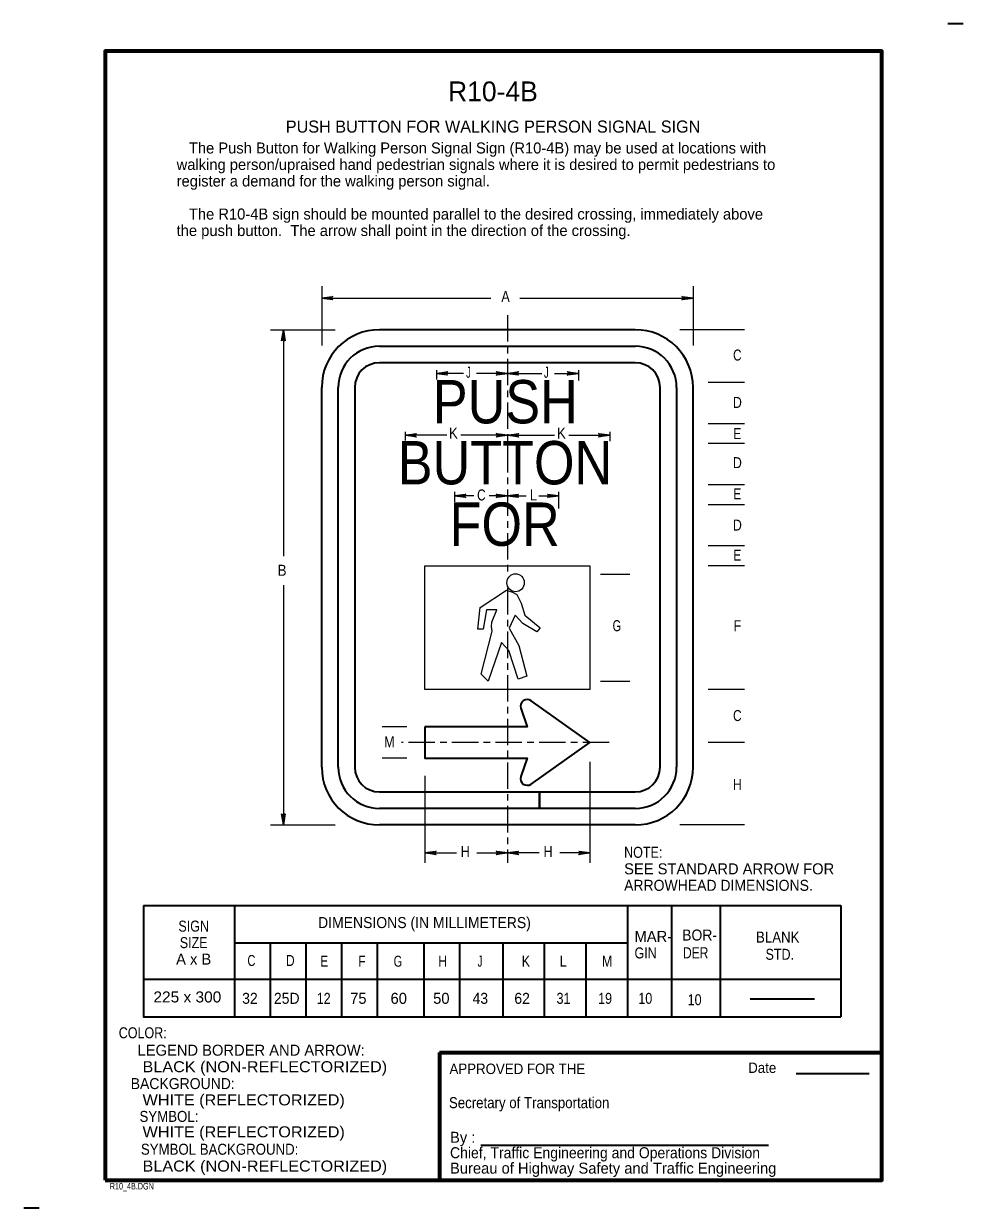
# Model space of a CAD drawing. Extents: x -13 to 209, y -30 to 60.
# Drawn here: x -12.67 to 8.68, y -16.28 to 10.63 of the extents above; entities that cross this region are included whole.
import ezdxf
from ezdxf.enums import TextEntityAlignment as Align

# ---------------------------------------------------------------- set-up
doc = ezdxf.new("R2010")
doc.units = 0
doc.header["$LTSCALE"] = 0.1
doc.linetypes.add('LONG_DASH_SHORT_DASH', pattern=[9.9, 6, -1.2, 1.5, -1.2])
doc.layers.add('1', color=7, linetype='Continuous', lineweight=35)
doc.layers.add('3', color=7, linetype='Continuous', lineweight=35)

msp = doc.modelspace()

# ---------------------------------------------------------------- linework, layer by layer
at = {"layer": '1'}
for p, q in [((8.6843, 10.633), (8.3343, 10.633)), ((4.8842, -13.217), (6.5468, -13.217)), ((-2.2782, -14.842), (4.2592, -14.842)), ((-12.3157, -16.2795), (-12.6658, -16.2795))]:
    msp.add_line(p, q, dxfattribs=at)
at = {"layer": '1', "lineweight": 70}
for q in [(6.8342, -12.742), (-3.2157, -15.642)]:
    msp.add_line((-3.2157, -12.742), q, dxfattribs=at)
msp.add_lwpolyline([(-10.8157, -15.642), (6.8342, -15.642), (6.8342, 10.008), (-10.8157, 10.008)], close=True, dxfattribs=at)
at = {"layer": '3', "lineweight": 25}
for p, q in [((-5.8936, 4.6688), (-5.8936, 3.3195)), ((2.5439, 4.6688), (2.5439, 3.3195)), ((-5.8936, 4.3976), (-2.0528, 4.3976)), ((-1.393, 4.3976), (2.5439, 4.3976)), ((-7.0587, 3.6803), (-5.5905, 3.6803)), ((-6.7644, 3.6803), (-6.7644, -1.4665)), ((3.709, 3.6803), (2.2408, 3.6803)), ((-3.2874, 2.7626), (-3.2874, 2.5488)), ((-0.0624, 2.7626), (-0.0624, 2.5305)), ((-2.6729, 2.6881), (-3.2874, 2.6881)), ((-1.6749, 2.6881), (-2.3796, 2.6881)), ((-1.6749, 2.6881), (-0.8889, 2.6881)), ((-0.6079, 2.6881), (-0.0624, 2.6881)), ((3.709, 2.4802), (2.8895, 2.4802)), ((-3.9999, 1.3631), (-3.9999, 1.1615)), ((0.6501, 1.3631), (0.6501, 1.1493)), ((3.709, 1.5428), (2.8895, 1.5428)), ((-3.0516, 1.2825), (-3.9999, 1.2825)), ((-1.6749, 1.2825), (-2.734, 1.2825)), ((-1.6749, 1.2825), (-0.6018, 1.2825)), ((-0.278, 1.2825), (0.6501, 1.2825)), ((3.709, 1.0928), (2.8895, 1.0928)), ((3.709, 0.1552), (2.8895, 0.1552)), ((-2.8749, -0.0059), (-2.8749, -0.2259)), ((-2.4407, -0.0926), (-2.8749, -0.0926)), ((-1.6749, -0.0926), (-2.0864, -0.0926)), ((-1.6749, -0.0926), (-1.2494, -0.0926)), ((-0.9623, -0.0926), (-0.5124, -0.0926)), ((-0.5124, -0.0059), (-0.5124, -0.3786)), ((3.709, -0.2948), (2.8895, -0.2948)), ((3.709, -1.2323), (2.8895, -1.2323)), ((0.4395, -1.8725), (1.1096, -1.8725)), ((3.709, -1.6823), (2.8895, -1.6823)), ((-6.7644, -2.1265), (-6.7644, -7.5697)), ((0.4395, -4.3045), (1.1096, -4.3045)), ((3.709, -4.4947), (2.8895, -4.4947)), ((-3.959, -5.3385), (-4.521, -5.3385)), ((3.709, -5.6947), (2.8895, -5.6947)), ((-3.959, -6.051), (-4.521, -6.051)), ((0.2001, -6.1357), (0.2001, -8.4337)), ((-3.5499, -6.4536), (-3.5499, -8.4337)), ((-7.0587, -7.5697), (-5.5905, -7.5697)), ((3.709, -7.5697), (2.2408, -7.5697)), ((-3.5499, -8.2054), (-2.8317, -8.2054)), ((-2.3674, -8.2054), (-1.6749, -8.2054)), ((-0.95, -8.2054), (-1.6749, -8.2054)), ((0.2001, -8.2054), (-0.4856, -8.2054))]:
    msp.add_line(p, q, dxfattribs=at)
at = {"layer": '3', "linetype": 'LONG_DASH_SHORT_DASH', "lineweight": 25}
for p, q in [((-1.6749, 4.0096), (-1.6749, -1.8979)), ((-1.6749, -2.1885), (-1.6749, -8.4337)), ((0.6354, -5.6947), (-4.0811, -5.6947))]:
    msp.add_line(p, q, dxfattribs=at)
at = {"layer": '3'}
for p, q in [((1.2314, 3.6803), (-4.5811, 3.6803)), ((-4.5811, 3.3053), (1.2314, 3.3053)), ((1.2314, 2.9303), (-4.5811, 2.9303)), ((-5.8936, -6.2572), (-5.8936, 2.3678)), ((-5.5186, -6.2572), (-5.5186, 2.3678)), ((-5.1436, 2.3678), (-5.1436, -6.2572)), ((1.7939, -6.2572), (1.7939, 2.3678)), ((2.1689, 2.3678), (2.1689, -6.2572)), ((2.5439, -6.2572), (2.5439, 2.3678)), ((-4.5811, -6.8197), (-0.9436, -6.8197)), ((1.2314, -7.5697), (-4.5811, -7.5697)), ((-9.9407, -9.3999), (5.905, -9.3999)), ((-7.8776, -9.3999), (-7.8776, -11.9311)), ((1.0575, -9.3999), (1.0575, -11.9311)), ((2.0575, -9.3999), (2.0575, -11.9311)), ((5.905, -9.3999), (5.905, -11.9311)), ((3.1586, -9.4311), (3.1586, -11.9311)), ((1.0575, -10.2592), (-7.8776, -10.2592)), ((-7.0676, -10.2592), (-7.0676, -11.9311)), ((-6.2576, -10.2592), (-6.2576, -11.9311)), ((-5.4476, -10.2592), (-5.4476, -11.9311)), ((-4.6376, -10.2592), (-4.6376, -11.9311)), ((-3.5745, -10.2592), (-3.5745, -11.9311)), ((-2.7645, -10.2592), (-2.7645, -11.9311)), ((-1.7775, -10.2592), (-1.7775, -11.9311)), ((-0.8407, -10.2592), (-0.8407, -11.9311)), ((0.1084, -10.2592), (0.1084, -11.9311)), ((-9.9407, -11.0717), (5.905, -11.0717)), ((5.3064, -11.5279), (3.8381, -11.5279))]:
    msp.add_line(p, q, dxfattribs=at)
at = {"layer": '3', "lineweight": 25}
for points in [[(-5.652, 4.3673), (-5.661, 4.3848), (-5.8936, 4.3976), (-5.652, 4.3673), (-5.6396, 4.3567), (-5.8936, 4.3976), (-5.6612, 4.4091), (-5.6528, 4.4264), (-5.8936, 4.3976), (-5.6396, 4.438), (-5.6528, 4.4264)], [(2.3022, 4.428), (2.3113, 4.4105), (2.5439, 4.3976), (2.3022, 4.428), (2.2899, 4.4385), (2.5439, 4.3976), (2.3115, 4.3861), (2.303, 4.3689), (2.5439, 4.3976), (2.2899, 4.3573), (2.303, 4.3689)], [(-6.7948, 3.4386), (-6.7773, 3.4476), (-6.7644, 3.6803), (-6.7948, 3.4386), (-6.8053, 3.4263), (-6.7644, 3.6803), (-6.7529, 3.4479), (-6.7356, 3.4394), (-6.7644, 3.6803), (-6.724, 3.4263), (-6.7356, 3.4394)], [(-3.0457, 2.6578), (-3.0547, 2.6753), (-3.2874, 2.6881), (-3.0457, 2.6578), (-3.0334, 2.6473), (-3.2874, 2.6881), (-3.055, 2.6996), (-3.0465, 2.7169), (-3.2874, 2.6881), (-3.0334, 2.7285), (-3.0465, 2.7169)], [(-1.9165, 2.7185), (-1.9075, 2.701), (-1.6749, 2.6881), (-1.9165, 2.7185), (-1.9289, 2.729), (-1.6749, 2.6881), (-1.9073, 2.6766), (-1.9158, 2.6594), (-1.6749, 2.6881), (-1.9289, 2.6478), (-1.9158, 2.6594)], [(-1.4333, 2.6578), (-1.4423, 2.6753), (-1.6749, 2.6881), (-1.4333, 2.6578), (-1.4209, 2.6473), (-1.6749, 2.6881), (-1.4425, 2.6996), (-1.434, 2.7169), (-1.6749, 2.6881), (-1.4209, 2.7285), (-1.434, 2.7169)], [(-0.304, 2.7185), (-0.295, 2.701), (-0.0624, 2.6881), (-0.304, 2.7185), (-0.3164, 2.729), (-0.0624, 2.6881), (-0.2948, 2.6766), (-0.3033, 2.6594), (-0.0624, 2.6881), (-0.3164, 2.6478), (-0.3033, 2.6594)], [(-3.7582, 1.2521), (-3.7673, 1.2696), (-3.9999, 1.2825), (-3.7582, 1.2521), (-3.7459, 1.2416), (-3.9999, 1.2825), (-3.7675, 1.294), (-3.759, 1.3113), (-3.9999, 1.2825), (-3.7459, 1.3229), (-3.759, 1.3113)], [(-1.9165, 1.3129), (-1.9075, 1.2954), (-1.6749, 1.2825), (-1.9165, 1.3129), (-1.9289, 1.3234), (-1.6749, 1.2825), (-1.9073, 1.271), (-1.9158, 1.2537), (-1.6749, 1.2825), (-1.9289, 1.2421), (-1.9158, 1.2537)], [(-1.4333, 1.2521), (-1.4423, 1.2696), (-1.6749, 1.2825), (-1.4333, 1.2521), (-1.4209, 1.2416), (-1.6749, 1.2825), (-1.4425, 1.294), (-1.434, 1.3113), (-1.6749, 1.2825), (-1.4209, 1.3229), (-1.434, 1.3113)], [(0.4085, 1.3129), (0.4175, 1.2954), (0.6501, 1.2825), (0.4085, 1.3129), (0.3961, 1.3234), (0.6501, 1.2825), (0.4178, 1.271), (0.4093, 1.2537), (0.6501, 1.2825), (0.3961, 1.2421), (0.4093, 1.2537)], [(-2.6332, -0.123), (-2.6423, -0.1055), (-2.8749, -0.0926), (-2.6332, -0.123), (-2.6209, -0.1335), (-2.8749, -0.0926), (-2.6425, -0.0811), (-2.634, -0.0639), (-2.8749, -0.0926), (-2.6209, -0.0522), (-2.634, -0.0639)], [(-1.9165, -0.0622), (-1.9075, -0.0798), (-1.6749, -0.0926), (-1.9165, -0.0622), (-1.9289, -0.0518), (-1.6749, -0.0926), (-1.9073, -0.1041), (-1.9158, -0.1214), (-1.6749, -0.0926), (-1.9289, -0.133), (-1.9158, -0.1214)], [(-1.4333, -0.123), (-1.4423, -0.1055), (-1.6749, -0.0926), (-1.4333, -0.123), (-1.4209, -0.1335), (-1.6749, -0.0926), (-1.4425, -0.0811), (-1.434, -0.0639), (-1.6749, -0.0926), (-1.4209, -0.0522), (-1.434, -0.0639)], [(-0.754, -0.0622), (-0.745, -0.0798), (-0.5124, -0.0926), (-0.754, -0.0622), (-0.7664, -0.0518), (-0.5124, -0.0926), (-0.7448, -0.1041), (-0.7532, -0.1214), (-0.5124, -0.0926), (-0.7664, -0.133), (-0.7532, -0.1214)], [(-6.734, -7.3281), (-6.7515, -7.3371), (-6.7644, -7.5697), (-6.734, -7.3281), (-6.7235, -7.3158), (-6.7644, -7.5697), (-6.7759, -7.3374), (-6.7931, -7.3289), (-6.7644, -7.5697), (-6.8048, -7.3158), (-6.7931, -7.3289)], [(-3.3083, -8.2357), (-3.3173, -8.2182), (-3.5499, -8.2054), (-3.3083, -8.2357), (-3.2959, -8.2462), (-3.5499, -8.2054), (-3.3175, -8.1939), (-3.309, -8.1766), (-3.5499, -8.2054), (-3.2959, -8.165), (-3.309, -8.1766)], [(-1.9165, -8.175), (-1.9075, -8.1925), (-1.6749, -8.2054), (-1.9165, -8.175), (-1.9289, -8.1645), (-1.6749, -8.2054), (-1.9073, -8.2169), (-1.9158, -8.2341), (-1.6749, -8.2054), (-1.9289, -8.2458), (-1.9158, -8.2341)], [(-1.4333, -8.2357), (-1.4423, -8.2182), (-1.6749, -8.2054), (-1.4333, -8.2357), (-1.4209, -8.2462), (-1.6749, -8.2054), (-1.4425, -8.1939), (-1.434, -8.1766), (-1.6749, -8.2054), (-1.4209, -8.165), (-1.434, -8.1766)], [(-0.0415, -8.175), (-0.0325, -8.1925), (0.2001, -8.2054), (-0.0415, -8.175), (-0.0539, -8.1645), (0.2001, -8.2054), (-0.0323, -8.2169), (-0.0408, -8.2341), (0.2001, -8.2054), (-0.0539, -8.2458), (-0.0408, -8.2341)]]:
    msp.add_lwpolyline(points, dxfattribs=at)
for points in [[(0.2001, -4.4947), (-3.5499, -4.4947), (-3.5499, -1.6823), (0.2001, -1.6823)], [(-0.9296, -3.0885), (-1.0092, -3.1823), (-1.3234, -2.9948), (-1.4968, -2.8073), (-1.6374, -3.1025), (-1.4124, -3.4962), (-1.2343, -4.19), (-1.4311, -4.2604), (-1.6421, -3.6088), (-1.8061, -3.426), (-2.1155, -4.3072), (-2.2702, -4.1431), (-2.0217, -3.1681), (-2.0311, -3.1119), (-2.0359, -3.065), (-2.0359, -3.0322), (-2.0311, -3.0041), (-2.0265, -2.9619), (-1.9186, -2.6854), (-2.1484, -2.6854), (-2.228, -3.1212), (-2.3453, -3.1212), (-2.2936, -2.6291), (-1.6984, -2.2354), (-1.5624, -2.2822), (-1.4592, -2.3338), (-1.3655, -2.5354), (-1.2811, -2.8025)]]:
    msp.add_lwpolyline(points, close=True, dxfattribs=at)
at = {"layer": '3'}
for points in [[(-1.1382, -6.6421), (0.2001, -5.6947), (-1.1382, -4.7473)], [(-1.3674, -4.9165), (-1.2288, -5.3385), (-3.5499, -5.3385)], [(-3.5499, -5.3385), (-3.5499, -6.051), (-1.2288, -6.051), (-1.3674, -6.4729)], [(-0.9436, -6.8197), (-0.9436, -7.1947), (-4.5811, -7.1947)], [(1.2314, -7.1947), (-0.9436, -7.1947), (-0.9436, -6.8197), (1.2314, -6.8197)], [(-9.9407, -9.3999), (-9.9407, -11.9311), (5.905, -11.9311)]]:
    msp.add_lwpolyline(points, dxfattribs=at)
for centre, radius, start, end in [((-4.5811, 2.3678), 1.3125, 90, 180), ((1.2314, 2.3678), 1.3125, 0, 90), ((-4.5811, 2.3678), 0.9375, 90, 180), ((1.2314, 2.3678), 0.9375, 0, 90), ((-4.5811, 2.3678), 0.5625, 90, 180), ((1.2314, 2.3678), 0.5625, 0, 90), ((-1.2249, -4.8697), 0.15, 54.70583, 198.19147), ((-4.5811, -6.2572), 1.3125, 180, 270), ((-4.5811, -6.2572), 0.9375, 180, 270), ((-4.5811, -6.2572), 0.5625, 180, 270), ((1.2314, -6.2572), 1.3125, 270, 0), ((1.2314, -6.2572), 0.9375, 270, 0), ((1.2314, -6.2572), 0.5625, 270, 0), ((-1.2249, -6.5197), 0.15, 161.80853, 305.29417)]:
    msp.add_arc(centre, radius, start, end, dxfattribs=at)
at = {"layer": '3', "lineweight": 25}
msp.add_ellipse((-1.4892, -2.0668), major_axis=(0, -0.2046), ratio=0.957031, dxfattribs=at)

# ---------------------------------------------------------------- texts
at = {"layer": '1'}
for s, height, p in [('R10-4B', 0.45, (-2.0038, 8.8705)), ('PUSH BUTTON FOR WALKING PERSON SIGNAL SIGN', 0.275, (-2.0001, 8.158))]:
    msp.add_text(s, height=height, dxfattribs=at).set_placement(p, align=Align.CENTER)
for s, height, width, p in [('COLOR:', 0.25, 0.85, (-10.5059, -12.4171)), ('      BLACK (NON-REFLECTORIZED)', 0.25, 1.1, (-10.5783, -13.1877)), ('APPROVED FOR THE', 0.2375, 0.95, (-2.9908, -13.2295)), ('Date ', 0.2375, 0.95, (3.7968, -13.2045)), (' BACKGROUND:', 0.25, 0.95, (-10.3226, -13.5711)), ('      WHITE (REFLECTORIZED)', 0.25, 1.1, (-10.5783, -13.9411)), ('Secretary of Transportation', 0.25, 0.9, (-3.0032, -14.0045)), ('SYMBOL:', 0.25, 0.9, (-10.0339, -14.3165)), ('      WHITE (REFLECTORIZED)', 0.25, 1.1, (-10.5783, -14.6666)), ('SYMBOL BACKGROUND:', 0.25, 0.9, (-10.0026, -15.0623)), ('Chief, Traffic Engineering and Operations Division', 0.25, 0.95, (-2.9783, -15.142)), ('      BLACK (NON-REFLECTORIZED)', 0.25, 1.1, (-10.5783, -15.4445)), ('R10_4B.DGN', 0.15, 0.75, (-10.7086, -15.8518))]:
    msp.add_text(s, height=height, dxfattribs=dict(at, width=width)).set_placement(p)
for s, p in [('LEGEND BORDER AND ARROW:', (-10.0783, -12.8127)), ('By :', (-2.9783, -14.792)), ('Bureau of Highway Safety and Traffic Engineering', (-2.9783, -15.492))]:
    msp.add_text(s, height=0.25, dxfattribs=at).set_placement(p)
at = {"layer": '3'}
for s, p in [('   The Push Button for Walking Person Signal Sign (R10-4B) may be used at locations with', (-9.1904, 7.6843)), ('walking person/upraised hand pedestrian signals where it is desired to permit pedestrians to ', (-9.1904, 7.3093)), ('register a demand for the walking person signal.', (-9.1904, 6.9343)), ('   The R10-4B sign should be mounted parallel to the desired crossing, immediately above', (-9.1904, 6.1843)), ('the push button.  The arrow shall point in the direction of the crossing.', (-9.1904, 5.8093)), ('SEE STANDARD ARROW FOR', (0.9775, -8.692)), ('MAR-', (1.2135, -10.228)), ('75', (-5.2474, -11.6342)), ('60', (-4.3296, -11.6342)), ('50', (-3.3619, -11.6342))]:
    msp.add_text(s, height=0.25, dxfattribs=at).set_placement(p)
for s, height, width, p in [('A', 0.25, 0.85, (-1.7167, 4.3124)), ('C', 0.25, 0.8, (3.5494, 2.98)), ('J', 0.25, 0.65, (-2.5598, 2.589)), ('J', 0.25, 0.65, (-0.7899, 2.589)), ('PUSH', 0.9849, 0.9, (-1.7223, 1.5526)), ('D', 0.25, 0.85, (3.5496, 1.9045)), ('K', 0.25, 0.9, (-2.9021, 1.2078)), ('K', 0.25, 0.9, (-0.4477, 1.2078)), ('E', 0.25, 0.8, (3.5494, 1.1955)), ('BUTTON', 0.9849, 0.9, (-1.7297, 0.167)), ('D', 0.25, 0.85, (3.5496, 0.5353)), ('C', 0.25, 0.8, (-2.2667, -0.198)), ('L', 0.25, 0.9, (-1.0831, -0.198)), ('E', 0.25, 0.8, (3.5494, -0.1738)), ('FOR', 0.9849, 0.9, (-1.7372, -1.2292)), ('D', 0.25, 0.85, (3.5496, -0.8825)), ('E', 0.25, 0.8, (3.5494, -1.567)), ('B', 0.25, 0.9, (-6.7938, -1.9093)), ('G', 0.25, 0.75, (0.8125, -3.1684)), ('F', 0.25, 0.85, (3.5495, -3.1684)), ('C', 0.25, 0.8, (3.5494, -5.2098)), ('M', 0.25, 0.85, (-4.3562, -5.8086)), ('H', 0.25, 0.85, (3.5495, -6.7743)), ('H', 0.25, 0.85, (-2.6332, -8.3021)), ('H', 0.25, 0.85, (-0.7514, -8.3021)), ('SIGN', 0.25, 0.85, (-8.803, -9.9936)), ('SIZE', 0.25, 0.85, (-8.803, -10.3686)), ('C', 0.25, 0.75, (-7.4908, -10.7749)), ('D', 0.25, 0.8, (-6.6071, -10.7749)), ('E', 0.25, 0.8, (-5.8353, -10.7905)), ('F', 0.25, 0.8, (-4.9816, -10.7905)), ('G', 0.25, 0.75, (-4.1623, -10.7905)), ('H', 0.25, 0.8, (-3.1458, -10.7905)), ('J', 0.25, 0.65, (-2.2974, -10.7905)), ('K', 0.25, 0.85, (-1.256, -10.7905)), ('L', 0.25, 0.85, (-0.407, -10.7905)), ('M', 0.25, 0.85, (0.5906, -10.7905)), ('225 x 300', 0.25, 1.05, (-8.9471, -11.603))]:
    msp.add_text(s, height=height, dxfattribs=dict(at, width=width)).set_placement(p, align=Align.CENTER)
for s, height, width, p in [('NOTE:', 0.25, 0.85, (0.9775, -8.317)), ('ARROWHEAD DIMENSIONS.', 0.25, 0.95, (0.9775, -9.067)), ('DIMENSIONS (IN MILLIMETERS)', 0.25, 0.95, (-5.9769, -9.9132)), ('BOR-', 0.25, 0.95, (2.2959, -10.1967)), ('BLANK', 0.25, 0.9, (3.9741, -10.2436)), ('GIN', 0.25, 0.85, (1.2135, -10.603)), ('DER', 0.2552, 0.8, (2.3157, -10.603)), ('STD.', 0.25, 0.85, (4.1906, -10.6342)), ('32', 0.25, 0.95, (-7.7016, -11.6342)), ('25D', 0.25, 0.95, (-6.9801, -11.6342)), ('12', 0.25, 0.85, (-6.0071, -11.6342)), ('43', 0.25, 0.95, (-2.467, -11.6342)), ('62', 0.25, 0.95, (-1.517, -11.6342)), ('31', 0.25, 0.85, (-0.5579, -11.6342)), ('19', 0.25, 0.85, (0.3865, -11.6342)), ('10', 0.25, 0.85, (1.3004, -11.6342)), ('10', 0.25, 0.85, (2.4211, -11.6655))]:
    msp.add_text(s, height=height, dxfattribs=dict(at, width=width)).set_placement(p)
msp.add_text('A x B', height=0.25, dxfattribs=at).set_placement((-8.803, -10.7436), align=Align.CENTER)

doc.saveas('drawing.dxf')
